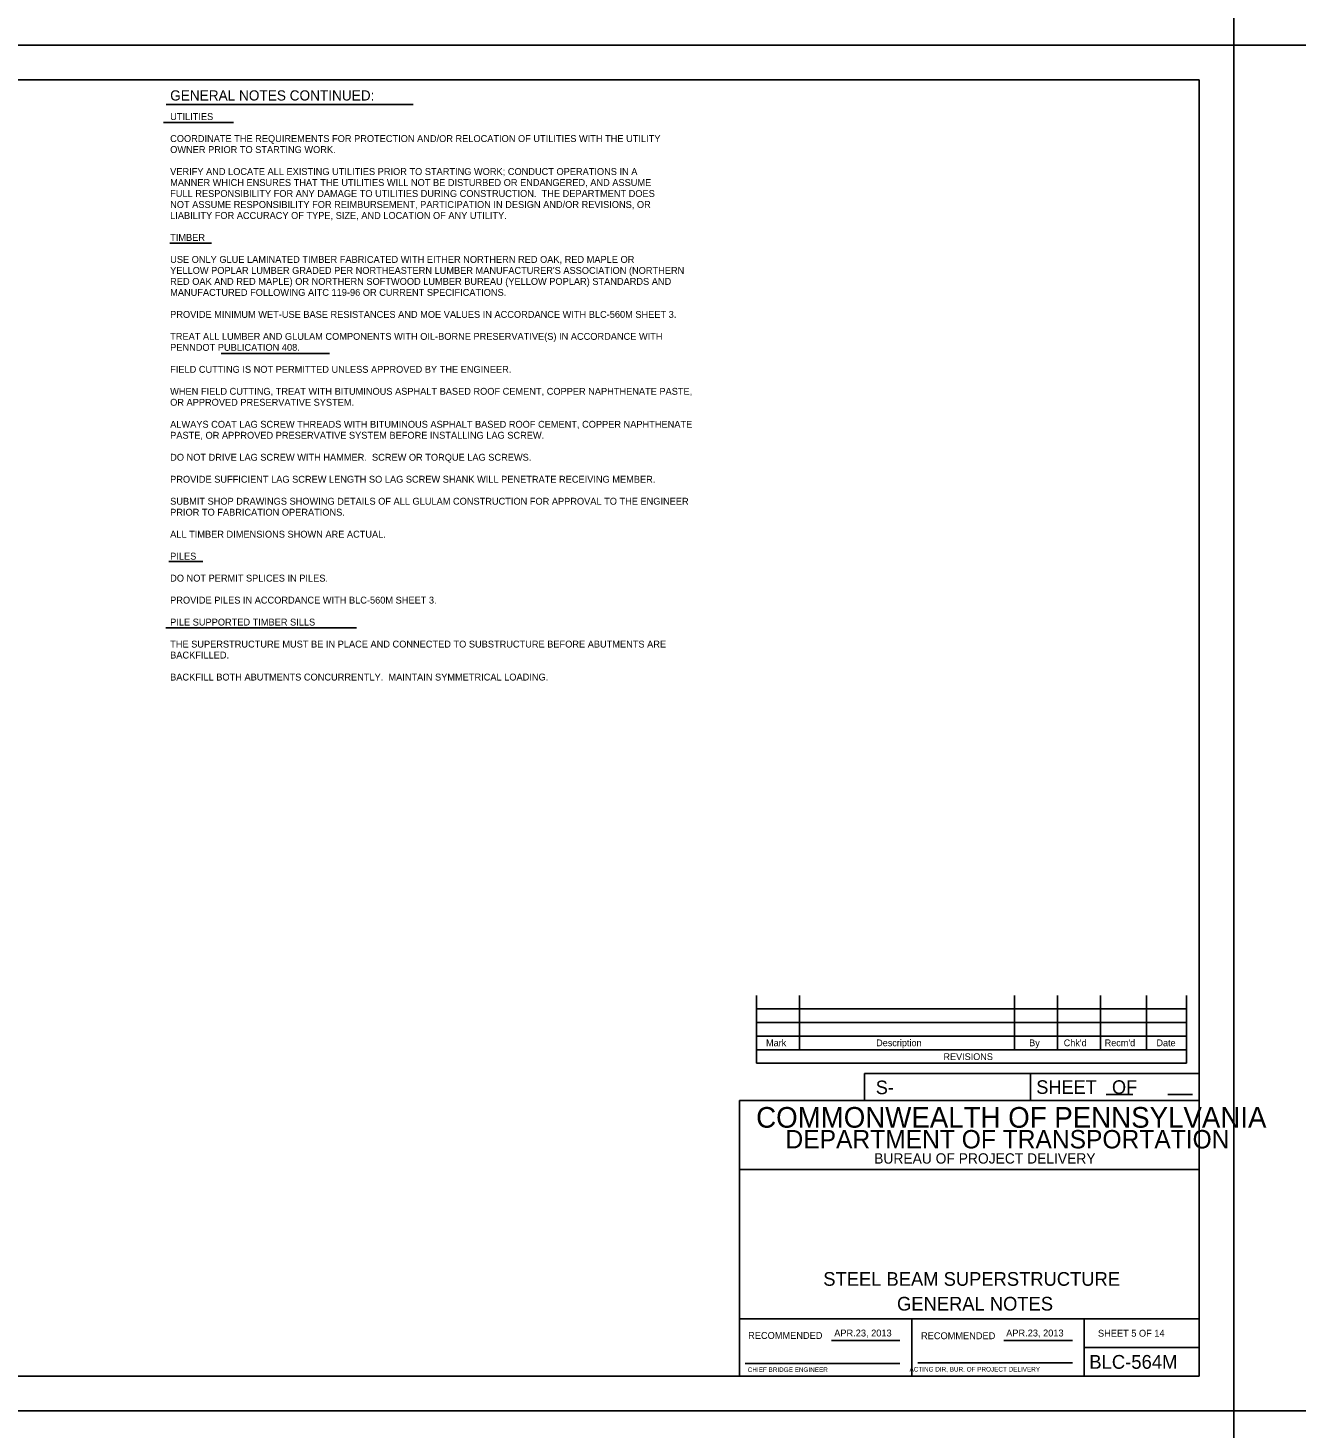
# Model space of a CAD drawing. Extents: x 638175 to 640495, y 294277 to 298435.
# Drawn here: x 638752 to 639304, y 295458 to 296067 of the extents above; entities that cross this region are included whole.
import ezdxf

# ---------------------------------------------------------------- set-up
doc = ezdxf.new("R2010")
doc.units = 0
for name, color, linetype in [('1', 7, 'Continuous'), ('2', 7, 'Continuous'), ('4', 7, 'Continuous'), ('PLT-BNDY', 7, 'Continuous')]:
    doc.layers.add(name, color=color, linetype=linetype)

msp = doc.modelspace()

# ---------------------------------------------------------------- linework, layer by layer
at = {"layer": '2'}
for p, q in [((638475.46, 296044.46), (639261.46, 296044.46)), ((639261.46, 296044.46), (639261.46, 295480.46)), ((638810.87, 296025.88), (638841.36, 296025.88)), ((638813.6, 295973.34), (638831.76, 295973.34)), ((638883.05, 295925.31), (638835.88, 295925.31)), ((638813.2, 295834.84), (638828.03, 295834.84)), ((638811.87, 295806.01), (638894.88, 295806.01)), ((639068.92, 295646.15), (639068.92, 295616.62)), ((639087.62, 295646.15), (639087.62, 295622.53)), ((639181.13, 295646.15), (639181.13, 295622.53)), ((639199.83, 295646.15), (639199.83, 295622.53)), ((639218.53, 295646.15), (639218.53, 295622.53)), ((639238.59, 295646.15), (639238.59, 295622.53)), ((639255.94, 295646.15), (639255.94, 295616.62)), ((639255.94, 295640.24), (639068.92, 295640.24)), ((639255.94, 295634.34), (639068.92, 295634.34)), ((639255.94, 295628.43), (639068.92, 295628.43)), ((639255.94, 295622.53), (639068.92, 295622.53)), ((639255.94, 295616.62), (639068.92, 295616.62)), ((639261.46, 295612.11), (639115.78, 295612.11)), ((639115.78, 295612.11), (639115.78, 295600.46)), ((639188.09, 295612.11), (639188.09, 295600.46)), ((639220.95, 295603), (639232.6, 295603)), ((639247.83, 295603), (639258.56, 295603)), ((639261.46, 295600.46), (639061.46, 295600.46)), ((639061.46, 295600.46), (639061.46, 295480.46)), ((639261.46, 295570.46), (639061.46, 295570.46)), ((639261.46, 295505.46), (639061.46, 295505.46)), ((639136.46, 295480.46), (639136.46, 295505.46)), ((639211.46, 295505.46), (639211.46, 295480.46)), ((639101.42, 295495.96), (639131.19, 295495.96)), ((639176.42, 295495.96), (639206.33, 295495.96)), ((639211.46, 295492.96), (639261.46, 295492.96)), ((639063.96, 295485.96), (639131.19, 295485.96)), ((639139.08, 295486.33), (639206.33, 295486.33)), ((639261.46, 295480.46), (638475.46, 295480.46))]:
    msp.add_line(p, q, dxfattribs=at)
at = {"layer": '4'}
msp.add_line((638811.98, 296033.65), (638919.52, 296033.65), dxfattribs=at)
at = {"layer": 'PLT-BNDY'}
for points in [[(638435.46, 296653.46), (639276.46, 296653.46), (639276.46, 296059.46), (638435.46, 296059.46)], [(639276.46, 296653.46), (640117.46, 296653.46), (640117.46, 296059.46), (639276.46, 296059.46)], [(638435.46, 296059.46), (639276.46, 296059.46), (639276.46, 295465.46), (638435.46, 295465.46)], [(639276.46, 296059.46), (640117.46, 296059.46), (640117.46, 295465.46), (639276.46, 295465.46)], [(638435.46, 295465.46), (639276.46, 295465.46), (639276.46, 294871.46), (638435.46, 294871.46)], [(639276.46, 295465.46), (640117.46, 295465.46), (640117.46, 294871.46), (639276.46, 294871.46)]]:
    msp.add_lwpolyline(points, close=True, dxfattribs=at)

# ---------------------------------------------------------------- texts
at = {"layer": '1'}
msp.add_text('SHEET 5 OF 14', height=3, dxfattribs=at).set_placement((639217.42, 295497.67))
at = {"layer": '2'}
for s, height, p in [('GENERAL NOTES CONTINUED:', 4.4292, (638813.76, 296035.41)), ('UTILITIES', 3, (638813.76, 296026.92)), ('COORDINATE THE REQUIREMENTS FOR PROTECTION AND/OR RELOCATION OF UTILITIES WITH THE UTILITY', 3, (638813.76, 296017.36)), ('OWNER PRIOR TO STARTING WORK.', 3, (638813.76, 296012.58)), ('VERIFY AND LOCATE ALL EXISTING UTILITIES PRIOR TO STARTING WORK; CONDUCT OPERATIONS IN A', 3, (638813.76, 296003.02)), ('MANNER WHICH ENSURES THAT THE UTILITIES WILL NOT BE DISTURBED OR ENDANGERED, AND ASSUME', 3, (638813.76, 295998.24)), ('FULL RESPONSIBILITY FOR ANY DAMAGE TO UTILITIES DURING CONSTRUCTION.  THE DEPARTMENT DOES', 3, (638813.76, 295993.46)), ('NOT ASSUME RESPONSIBILITY FOR REIMBURSEMENT, PARTICIPATION IN DESIGN AND/OR REVISIONS, OR', 3, (638813.76, 295988.68)), ('LIABILITY FOR ACCURACY OF TYPE, SIZE, AND LOCATION OF ANY UTILITY.', 3, (638813.76, 295983.9)), ('TIMBER', 3, (638813.76, 295974.34)), ("YELLOW POPLAR LUMBER GRADED PER NORTHEASTERN LUMBER MANUFACTURER'S ASSOCIATION (NORTHERN", 3, (638813.76, 295960)), ('USE ONLY GLUE LAMINATED TIMBER FABRICATED WITH EITHER NORTHERN RED OAK, RED MAPLE OR ', 3, (638813.76, 295964.78)), ('RED OAK AND RED MAPLE) OR NORTHERN SOFTWOOD LUMBER BUREAU (YELLOW POPLAR) STANDARDS AND ', 3, (638813.76, 295955.22)), ('MANUFACTURED FOLLOWING AITC 119-96 OR CURRENT SPECIFICATIONS.', 3, (638813.76, 295950.43)), ('PROVIDE MINIMUM WET-USE BASE RESISTANCES AND MOE VALUES IN ACCORDANCE WITH BLC-560M SHEET 3.', 3, (638813.76, 295940.87)), ('TREAT ALL LUMBER AND GLULAM COMPONENTS WITH OIL-BORNE PRESERVATIVE(S) IN ACCORDANCE WITH', 3, (638813.76, 295931.31)), ('PENNDOT PUBLICATION 408.', 3, (638813.76, 295926.53)), ('FIELD CUTTING IS NOT PERMITTED UNLESS APPROVED BY THE ENGINEER.', 3, (638813.76, 295916.97)), ('WHEN FIELD CUTTING, TREAT WITH BITUMINOUS ASPHALT BASED ROOF CEMENT, COPPER NAPHTHENATE PASTE, ', 3, (638813.76, 295907.41)), ('OR APPROVED PRESERVATIVE SYSTEM.', 3, (638813.76, 295902.63)), ('ALWAYS COAT LAG SCREW THREADS WITH BITUMINOUS ASPHALT BASED ROOF CEMENT, COPPER NAPHTHENATE', 3, (638813.76, 295893.07)), ('PASTE, OR APPROVED PRESERVATIVE SYSTEM BEFORE INSTALLING LAG SCREW.', 3, (638813.76, 295888.29)), ('DO NOT DRIVE LAG SCREW WITH HAMMER.  SCREW OR TORQUE LAG SCREWS.', 3, (638813.76, 295878.72)), ('PROVIDE SUFFICIENT LAG SCREW LENGTH SO LAG SCREW SHANK WILL PENETRATE RECEIVING MEMBER.', 3, (638813.76, 295869.16)), ('SUBMIT SHOP DRAWINGS SHOWING DETAILS OF ALL GLULAM CONSTRUCTION FOR APPROVAL TO THE ENGINEER ', 3, (638813.76, 295859.6)), ('PRIOR TO FABRICATION OPERATIONS.', 3, (638813.76, 295854.82)), ('ALL TIMBER DIMENSIONS SHOWN ARE ACTUAL.', 3, (638813.76, 295845.26)), ('PILES', 3, (638813.76, 295835.7)), ('DO NOT PERMIT SPLICES IN PILES.', 3, (638813.76, 295826.14)), ('PROVIDE PILES IN ACCORDANCE WITH BLC-560M SHEET 3.', 3, (638813.76, 295816.58)), ('PILE SUPPORTED TIMBER SILLS', 3, (638813.76, 295807.02)), ('THE SUPERSTRUCTURE MUST BE IN PLACE AND CONNECTED TO SUBSTRUCTURE BEFORE ABUTMENTS ARE ', 3, (638813.76, 295797.45)), ('BACKFILLED.', 3, (638813.76, 295792.67)), ('BACKFILL BOTH ABUTMENTS CONCURRENTLY.  MAINTAIN SYMMETRICAL LOADING.', 3, (638813.76, 295783.11)), ('Mark', 2.952, (639073.02, 295624.03)), ('Description', 2.9523, (639120.92, 295624.03)), ('By', 2.952, (639187.49, 295624.03)), ("Chk'd", 2.952, (639202.52, 295624.03)), ("Recm'd", 2.953, (639220.33, 295624.03)), ('Date', 2.952, (639242.86, 295624.03)), ('REVISIONS', 2.952, (639150.2, 295618.01)), ('S-', 5.905, (639120.73, 295603.17)), ('COMMONWEALTH OF PENNSYLVANIA', 9, (639068.71, 295588.58)), ('DEPARTMENT OF TRANSPORTATION', 8.0002, (639081.46, 295579.58)), ('BUREAU OF PROJECT DELIVERY', 4.5, (639120.05, 295572.96)), ('GENERAL NOTES', 5.9714, (639129.99, 295509.04)), ('APR.23, 2013', 3, (639102.67, 295497.77)), ('APR.23, 2013', 3, (639177.48, 295497.77)), ('BLC-564M', 6, (639213.64, 295483.71)), ('CHIEF BRIDGE ENGINEER', 2.0002, (639065.05, 295482.33)), ('  ACTING DIR, BUR. OF PROJECT DELIVERY', 2.0002, (639133.9, 295482.51))]:
    msp.add_text(s, height=height, dxfattribs=at).set_placement(p)
for s, height, p in [('SHEET   OF', 5.907, (639190.58, 295603.31)), ('RECOMMENDED', 3, (639065.23, 295496.71)), ('RECOMMENDED', 3, (639140.44, 295496.58))]:
    msp.add_text(s, height=height, rotation=360, dxfattribs=at).set_placement(p)
at = {"layer": '4'}
msp.add_text('STEEL BEAM SUPERSTRUCTURE', height=5.9714, dxfattribs=at).set_placement((639097.9, 295519.81))

doc.saveas('drawing.dxf')
